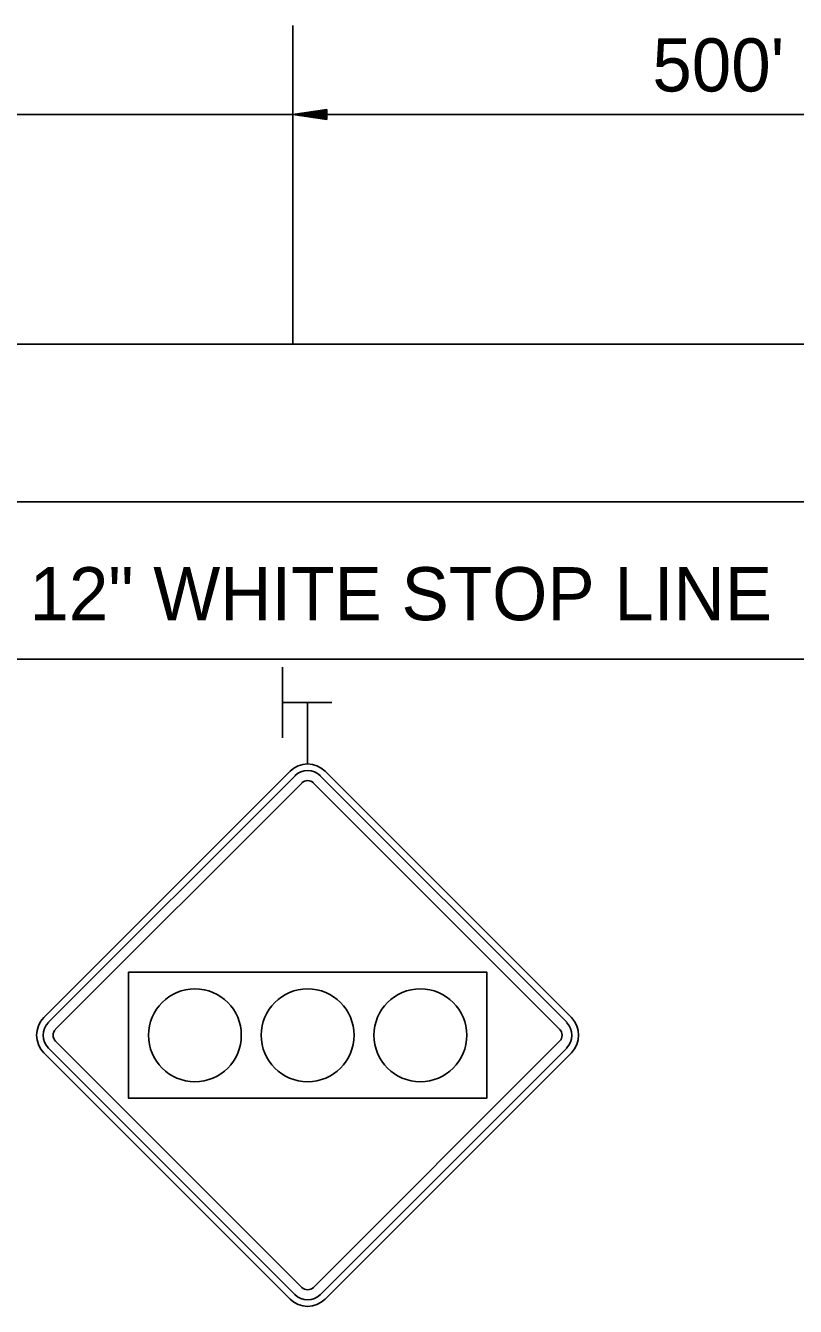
# Model space of a CAD drawing. Extents: x 1927831 to 1930787, y 596452 to 597699.
# Drawn here: x 1928473.3 to 1928560.4, y 597396.8 to 597541.6 of the extents above; entities that cross this region are included whole.
import ezdxf

# ---------------------------------------------------------------- set-up
doc = ezdxf.new("R2010")
doc.units = 0
for name, color, linetype in [('Default', 7, 'Continuous'), ('P_TC_Signs_Permanent', 7, 'Continuous'), ('R_Border', 7, 'Continuous')]:
    doc.layers.add(name, color=color, linetype=linetype)

msp = doc.modelspace()

# ---------------------------------------------------------------- linework, layer by layer
at = {"layer": 'Default'}
for p, q in [((1928503.55, 597541.61), (1928503.55, 597505.58)), ((1928404.65, 597531.57), (1928504.41, 597531.57)), ((1928507.39, 597532.14), (1928503.55, 597531.57)), ((1928503.55, 597531.57), (1928604.69, 597531.57)), ((1928507.39, 597530.99), (1928503.55, 597531.57)), ((1928507.39, 597532.05), (1928504.2, 597531.57)), ((1928507.39, 597531.09), (1928504.2, 597531.57)), ((1928507.39, 597531.95), (1928504.86, 597531.57)), ((1928507.39, 597531.18), (1928504.86, 597531.57)), ((1928507.39, 597531.85), (1928505.49, 597531.57)), ((1928507.39, 597531.28), (1928505.49, 597531.57)), ((1928507.39, 597531.75), (1928506.14, 597531.57)), ((1928507.39, 597531.38), (1928506.14, 597531.57)), ((1928507.39, 597531.66), (1928506.79, 597531.57)), ((1928507.39, 597531.48), (1928506.79, 597531.57)), ((1928507.39, 597530.99), (1928507.39, 597532.14)), ((1928044.85, 597505.58), (1929173.7, 597505.58)), ((1927908.3, 597487.79), (1929173.7, 597487.79)), ((1928044.85, 597470), (1929173.7, 597470)), ((1928502.38, 597461.1), (1928502.38, 597469.1)), ((1928502.49, 597465.08), (1928507.96, 597465.08))]:
    msp.add_line(p, q, dxfattribs=at)
at = {"layer": 'P_TC_Signs_Permanent'}
for p, q in [((1928475.4, 597429.47), (1928503.24, 597457.31)), ((1928475.93, 597428.94), (1928503.77, 597456.78)), ((1928506.69, 597456.78), (1928534.53, 597428.94)), ((1928507.22, 597457.31), (1928535.06, 597429.47)), ((1928504.56, 597455.99), (1928476.72, 597428.15)), ((1928533.73, 597428.15), (1928505.89, 597455.99)), ((1928503.77, 597398.18), (1928475.93, 597426.02)), ((1928476.72, 597426.82), (1928504.56, 597398.98)), ((1928505.89, 597398.98), (1928533.73, 597426.82)), ((1928534.53, 597426.02), (1928506.69, 597398.18)), ((1928503.24, 597397.65), (1928475.4, 597425.49)), ((1928535.06, 597425.49), (1928507.22, 597397.65))]:
    msp.add_line(p, q, dxfattribs=at)
msp.add_lwpolyline([(1928484.98, 597434.61), (1928484.98, 597420.36), (1928525.48, 597420.36), (1928525.48, 597434.61)], close=True, dxfattribs=at)
for centre in [(1928492.48, 597427.48), (1928505.23, 597427.48), (1928517.98, 597427.48)]:
    msp.add_circle(centre, 5.25, dxfattribs=at)
for centre, radius, start, end in [((1928505.23, 597455.33), 2.81, 45, 135), ((1928505.23, 597455.33), 2.06, 45, 135), ((1928505.23, 597455.33), 0.938, 45, 135), ((1928477.38, 597427.48), 2.81, 135, 225), ((1928477.38, 597427.48), 2.06, 135, 225), ((1928533.07, 597427.48), 2.06, 315, 45), ((1928533.07, 597427.48), 2.81, 315, 45), ((1928477.38, 597427.48), 0.938, 135, 225), ((1928533.07, 597427.48), 0.938, 315, 45), ((1928505.23, 597399.64), 0.938, 225, 315), ((1928505.23, 597399.64), 2.81, 225, 315), ((1928505.23, 597399.64), 2.06, 225, 315)]:
    msp.add_arc(centre, radius, start, end, dxfattribs=at)
at = {"layer": 'R_Border'}
msp.add_line((1928505.23, 597465.08), (1928505.23, 597458.14), dxfattribs=at)

# ---------------------------------------------------------------- texts
at = {"layer": 'Default'}
for s, p in [("500'", (1928544.22, 597534.16)), ('12" WHITE STOP LINE', (1928473.77, 597474.39))]:
    msp.add_text(s, height=6, rotation=360, dxfattribs=at).set_placement(p)

doc.saveas('drawing.dxf')
